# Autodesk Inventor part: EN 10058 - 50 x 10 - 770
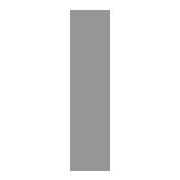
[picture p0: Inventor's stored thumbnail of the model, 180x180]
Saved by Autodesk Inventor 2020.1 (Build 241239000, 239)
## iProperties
_CCFamilyMember: 59
_CCFamilyDisplayName: DIN EN 10058 - Warmgewalzte Flachstahlprofile - Mehrzweck
_FrameMemberDoc: Frame Member File
_Version: 15.0.0
_GetPNFromCC: 1
IsCustomPart: 1
Created: 2019-01
Part Number: EN 10058 - 50 x 10 - 770
Material: Stahl, weich
Description: Warmgewalzte Flachstahlprofile - Mehrzweck
Document SubType Name: Modeling
Standard: DIN
Designer: lutzd
Standard Revision: 2004
Standards Organization: DIN
Language: de-DE
Size Designation: 50 x 10
Categories: <MemberInstance><Categories><Category DisplayName="Profile" InternalName="089c4875-fa83-4c05-b084-43b9cc11f5ed" Mnemonic="GRDR"><CategoryParameter DisplayName="
Stock Number: 50 x 10
Mass: 2996.3 g
Surface Area: 943.176 cm^2
Volume: 381.694 cm^3
Density: 7.85 g/cm^3
Appearance: Halbpoliert
G_L: 770,000 mm
G_W: 10,000 mm
G_H: 50,000 mm
DocNumber: ADSK-014140
Folder: .
Dimensions: 10x50x770 mm
Mass: 2,996 kg
Title: Profil-Bauteil
Author: lutzd
Revision Number: -
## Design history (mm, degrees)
node "Startebene"
node "Endebene"
sketch "Skizze"
  geometry: L1 (5, -25)-(-5, -25); L2 (-5, -25)-(-5, 25); L3 (-5, 25)-(5, 25); L4 (5, 25)-(5, -25); L5 (-6, 0)-(8, 0); L6 (0, -30)-(0, 40); L7 (0, 54)-(0, -44) reference; L8 (-9.2, 0)-(13.2, 0) reference
  constraints: 12 end point, 2 collinear, 2 parallel, 1 horizontal, 1 perpendicular
  dimensions: "d0" = 50 distance between parallel lines of L3 L1 (= G_W); "d1" = 10 distance between parallel lines of L4 L2 (= G_H); "d4" = 5 distance between parallel lines of L6 L4 (= 0.5 x d1); "d5" = 25 distance between parallel lines of L5 L3 (= 0.5 x d0)
extrude "Körper" new body sketch "Skizze" stored distance "d2" = 770 (= G_L); taper "d3" = 0 deg
node "Driven Length"
  sketch "Sketch3"
    geometry: L1 (0, 0)-(10, 0) reference
    constraints: 2 end point, 1 horizontal
  workplane "Work Plane3"
  sketch "Sketch4"
    geometry: L1 (-2, 0)-(12, 0) reference; L2 (-2, 770)-(12, 770) reference
    dimensions: "d9" = 770 distance between parallel lines of L1 L2 (derived)
sketch "Skizze5"
  geometry: L1 (0, 50)-(0, 0) reference; L2 (0, 25)-(770, 25); L3 (770, 50)-(770, 0) reference; 6 further points
  constraints: 6 point on line, 2 end point, 1 horizontal, 1 midpoint
  dimensions: "d10" = 75 distance from line of L3 point (695, 25); "d11" = 125 distance of point (570, 25) point (695, 25); "d12" = 125 distance of point (445, 25) point (570, 25) (= d11); "d13" = 125 distance of point (320, 25) point (445, 25) (= d11); "d14" = 125 distance of point (195, 25) point (320, 25) (= d11); "d15" = 125 distance of point (195, 25) point (70, 25) (= d11)
hole "Bohrung1" sketch "Skizze5" at (695, 25), (570, 25), (445, 25), (320, 25), (195, 25), (70, 25) diameter "d16" = 8.376; stored, may be unused: countersink angle "d20" = 90 deg, drill point angle "d22" = 118 deg; dims "d17" = 20, "d18" = 4, "d19" = 2, "d21" = 27.3
body "Solid1"
other parameters: "G_W" = 50 [user parameter; used in 1 equation term], "G_H" = 10 [user parameter; used in 1 equation term], "G_L" = 770 (= d9) [user parameter; used in 1 equation term], "G_OFFSET_START" = 0 [user parameter; used in 1 equation term], "G_OFFSET_END" = 0 [user parameter; used in 1 equation term], "d6" = 0 (computed from G_OFFSET_START), "d8" = 90 deg, "MAS" = 0.393 [user parameter]
